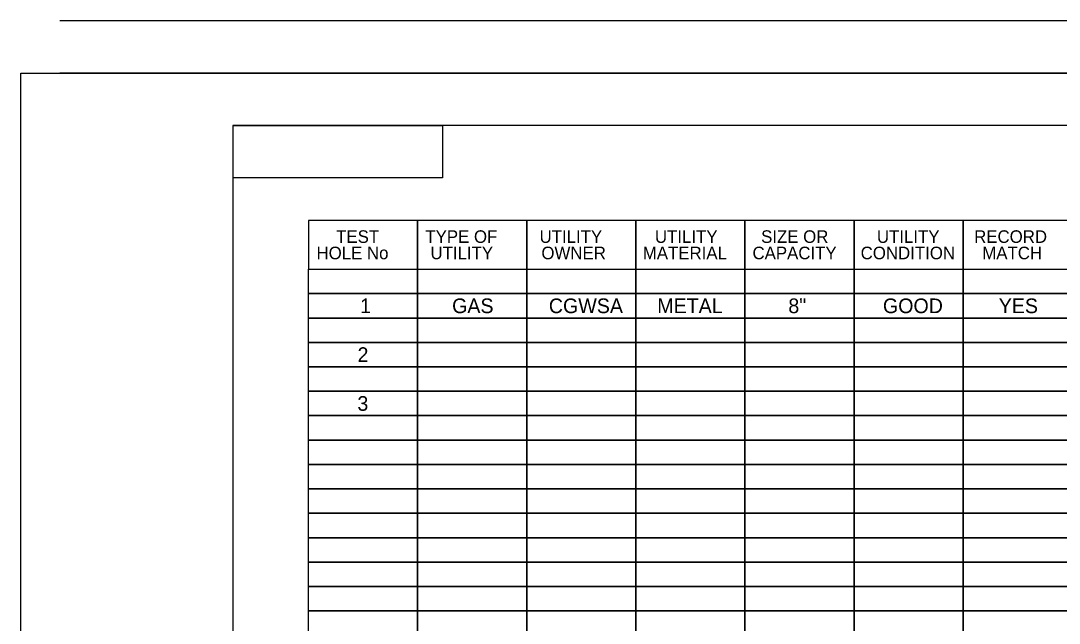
# Model space of a CAD drawing. Extents: x 14330 to 16126, y 15844 to 16994.
# Drawn here: x 14329.7 to 14825, y 16706 to 16993.6 of the extents above; entities that cross this region are included whole.
import ezdxf

# ---------------------------------------------------------------- set-up
doc = ezdxf.new("R2010")
doc.units = 0
for name, color, linetype in [('RD_SHT_Bndy', 7, 'Continuous'), ('RD_SHT_Iplotshp', 7, 'Continuous'), ('RD_SHT_Snap', 7, 'Continuous'), ('RD_SHT_TX', 7, 'Continuous')]:
    doc.layers.add(name, color=color, linetype=linetype)

msp = doc.modelspace()

# ---------------------------------------------------------------- linework, layer by layer
at = {"layer": 'RD_SHT_Bndy'}
for p, q in [((16108.25, 16993.63), (14348.25, 16993.63)), ((16108.25, 16968.63), (14348.25, 16968.63)), ((16105.85, 16943.63), (14430.85, 16943.63)), ((14430.85, 16943.63), (14430.85, 15893.63))]:
    msp.add_line(p, q, dxfattribs=at)
for points in [[(14430.9, 16918.63), (14430.9, 16943.63), (14530.9, 16943.63), (14530.9, 16918.63)], [(14466.94, 16875.02), (14518.98, 16875.02), (14518.98, 16898.33), (14466.94, 16898.33)], [(14518.98, 16875.02), (14571.02, 16875.02), (14571.02, 16898.33), (14518.98, 16898.33)], [(14571.02, 16875.02), (14623.07, 16875.02), (14623.07, 16898.33), (14571.02, 16898.33)], [(14623.07, 16875.02), (14675.11, 16875.02), (14675.11, 16898.33), (14623.07, 16898.33)], [(14675.11, 16875.02), (14727.15, 16875.02), (14727.15, 16898.33), (14675.11, 16898.33)], [(14727.15, 16875.02), (14779.19, 16875.02), (14779.19, 16898.33), (14727.15, 16898.33)], [(14779.19, 16875.02), (14831.23, 16875.02), (14831.23, 16898.33), (14779.19, 16898.33)], [(14518.98, 16863.36), (14466.94, 16863.36), (14466.94, 16875.02), (14518.98, 16875.02)], [(14571.02, 16863.36), (14518.98, 16863.36), (14518.98, 16875.02), (14571.02, 16875.02)], [(14623.07, 16863.36), (14571.02, 16863.36), (14571.02, 16875.02), (14623.07, 16875.02)], [(14675.11, 16863.36), (14623.07, 16863.36), (14623.07, 16875.02), (14675.11, 16875.02)], [(14727.15, 16863.36), (14675.11, 16863.36), (14675.11, 16875.02), (14727.15, 16875.02)], [(14779.19, 16863.36), (14727.15, 16863.36), (14727.15, 16875.02), (14779.19, 16875.02)], [(14831.23, 16863.36), (14779.19, 16863.36), (14779.19, 16875.02), (14831.23, 16875.02)], [(14518.98, 16851.71), (14466.94, 16851.71), (14466.94, 16863.36), (14518.98, 16863.36)], [(14571.02, 16851.71), (14518.98, 16851.71), (14518.98, 16863.36), (14571.02, 16863.36)], [(14623.07, 16851.71), (14571.02, 16851.71), (14571.02, 16863.36), (14623.07, 16863.36)], [(14675.11, 16851.71), (14623.07, 16851.71), (14623.07, 16863.36), (14675.11, 16863.36)], [(14727.15, 16851.71), (14675.11, 16851.71), (14675.11, 16863.36), (14727.15, 16863.36)], [(14779.19, 16851.71), (14727.15, 16851.71), (14727.15, 16863.36), (14779.19, 16863.36)], [(14831.23, 16851.71), (14779.19, 16851.71), (14779.19, 16863.36), (14831.23, 16863.36)], [(14518.98, 16840.05), (14466.94, 16840.05), (14466.94, 16851.71), (14518.98, 16851.71)], [(14571.02, 16840.05), (14518.98, 16840.05), (14518.98, 16851.71), (14571.02, 16851.71)], [(14623.07, 16840.05), (14571.02, 16840.05), (14571.02, 16851.71), (14623.07, 16851.71)], [(14675.11, 16840.05), (14623.07, 16840.05), (14623.07, 16851.71), (14675.11, 16851.71)], [(14727.15, 16840.05), (14675.11, 16840.05), (14675.11, 16851.71), (14727.15, 16851.71)], [(14779.19, 16840.05), (14727.15, 16840.05), (14727.15, 16851.71), (14779.19, 16851.71)], [(14831.23, 16840.05), (14779.19, 16840.05), (14779.19, 16851.71), (14831.23, 16851.71)], [(14518.98, 16828.4), (14466.94, 16828.4), (14466.94, 16840.05), (14518.98, 16840.05)], [(14571.02, 16828.4), (14518.98, 16828.4), (14518.98, 16840.05), (14571.02, 16840.05)], [(14623.07, 16828.4), (14571.02, 16828.4), (14571.02, 16840.05), (14623.07, 16840.05)], [(14675.11, 16828.4), (14623.07, 16828.4), (14623.07, 16840.05), (14675.11, 16840.05)], [(14727.15, 16828.4), (14675.11, 16828.4), (14675.11, 16840.05), (14727.15, 16840.05)], [(14779.19, 16828.4), (14727.15, 16828.4), (14727.15, 16840.05), (14779.19, 16840.05)], [(14831.23, 16828.4), (14779.19, 16828.4), (14779.19, 16840.05), (14831.23, 16840.05)], [(14518.98, 16816.74), (14466.94, 16816.74), (14466.94, 16828.4), (14518.98, 16828.4)], [(14571.02, 16816.74), (14518.98, 16816.74), (14518.98, 16828.4), (14571.02, 16828.4)], [(14623.07, 16816.74), (14571.02, 16816.74), (14571.02, 16828.4), (14623.07, 16828.4)], [(14675.11, 16816.74), (14623.07, 16816.74), (14623.07, 16828.4), (14675.11, 16828.4)], [(14727.15, 16816.74), (14675.11, 16816.74), (14675.11, 16828.4), (14727.15, 16828.4)], [(14779.19, 16816.74), (14727.15, 16816.74), (14727.15, 16828.4), (14779.19, 16828.4)], [(14831.23, 16816.74), (14779.19, 16816.74), (14779.19, 16828.4), (14831.23, 16828.4)], [(14518.98, 16805.09), (14466.94, 16805.09), (14466.94, 16816.74), (14518.98, 16816.74)], [(14571.02, 16805.09), (14518.98, 16805.09), (14518.98, 16816.74), (14571.02, 16816.74)], [(14623.07, 16805.09), (14571.02, 16805.09), (14571.02, 16816.74), (14623.07, 16816.74)], [(14675.11, 16805.09), (14623.07, 16805.09), (14623.07, 16816.74), (14675.11, 16816.74)], [(14727.15, 16805.09), (14675.11, 16805.09), (14675.11, 16816.74), (14727.15, 16816.74)], [(14779.19, 16805.09), (14727.15, 16805.09), (14727.15, 16816.74), (14779.19, 16816.74)], [(14831.23, 16805.09), (14779.19, 16805.09), (14779.19, 16816.74), (14831.23, 16816.74)], [(14518.98, 16793.43), (14466.94, 16793.43), (14466.94, 16805.09), (14518.98, 16805.09)], [(14571.02, 16793.43), (14518.98, 16793.43), (14518.98, 16805.09), (14571.02, 16805.09)], [(14623.07, 16793.43), (14571.02, 16793.43), (14571.02, 16805.09), (14623.07, 16805.09)], [(14675.11, 16793.43), (14623.07, 16793.43), (14623.07, 16805.09), (14675.11, 16805.09)], [(14727.15, 16793.43), (14675.11, 16793.43), (14675.11, 16805.09), (14727.15, 16805.09)], [(14779.19, 16793.43), (14727.15, 16793.43), (14727.15, 16805.09), (14779.19, 16805.09)], [(14831.23, 16793.43), (14779.19, 16793.43), (14779.19, 16805.09), (14831.23, 16805.09)], [(14518.98, 16781.78), (14466.94, 16781.78), (14466.94, 16793.43), (14518.98, 16793.43)], [(14571.02, 16781.78), (14518.98, 16781.78), (14518.98, 16793.43), (14571.02, 16793.43)], [(14623.07, 16781.78), (14571.02, 16781.78), (14571.02, 16793.43), (14623.07, 16793.43)], [(14675.11, 16781.78), (14623.07, 16781.78), (14623.07, 16793.43), (14675.11, 16793.43)], [(14727.15, 16781.78), (14675.11, 16781.78), (14675.11, 16793.43), (14727.15, 16793.43)], [(14779.19, 16781.78), (14727.15, 16781.78), (14727.15, 16793.43), (14779.19, 16793.43)], [(14831.23, 16781.78), (14779.19, 16781.78), (14779.19, 16793.43), (14831.23, 16793.43)], [(14518.98, 16770.12), (14466.94, 16770.12), (14466.94, 16781.78), (14518.98, 16781.78)], [(14571.02, 16770.12), (14518.98, 16770.12), (14518.98, 16781.78), (14571.02, 16781.78)], [(14623.07, 16770.12), (14571.02, 16770.12), (14571.02, 16781.78), (14623.07, 16781.78)], [(14675.11, 16770.12), (14623.07, 16770.12), (14623.07, 16781.78), (14675.11, 16781.78)], [(14727.15, 16770.12), (14675.11, 16770.12), (14675.11, 16781.78), (14727.15, 16781.78)], [(14779.19, 16770.12), (14727.15, 16770.12), (14727.15, 16781.78), (14779.19, 16781.78)], [(14831.23, 16770.12), (14779.19, 16770.12), (14779.19, 16781.78), (14831.23, 16781.78)], [(14518.98, 16758.47), (14466.94, 16758.47), (14466.94, 16770.12), (14518.98, 16770.12)], [(14571.02, 16758.47), (14518.98, 16758.47), (14518.98, 16770.12), (14571.02, 16770.12)], [(14623.07, 16758.47), (14571.02, 16758.47), (14571.02, 16770.12), (14623.07, 16770.12)], [(14675.11, 16758.47), (14623.07, 16758.47), (14623.07, 16770.12), (14675.11, 16770.12)], [(14727.15, 16758.47), (14675.11, 16758.47), (14675.11, 16770.12), (14727.15, 16770.12)], [(14779.19, 16758.47), (14727.15, 16758.47), (14727.15, 16770.12), (14779.19, 16770.12)], [(14831.23, 16758.47), (14779.19, 16758.47), (14779.19, 16770.12), (14831.23, 16770.12)], [(14518.98, 16746.81), (14466.94, 16746.81), (14466.94, 16758.47), (14518.98, 16758.47)], [(14571.02, 16746.81), (14518.98, 16746.81), (14518.98, 16758.47), (14571.02, 16758.47)], [(14623.07, 16746.81), (14571.02, 16746.81), (14571.02, 16758.47), (14623.07, 16758.47)], [(14675.11, 16746.81), (14623.07, 16746.81), (14623.07, 16758.47), (14675.11, 16758.47)], [(14727.15, 16746.81), (14675.11, 16746.81), (14675.11, 16758.47), (14727.15, 16758.47)], [(14779.19, 16746.81), (14727.15, 16746.81), (14727.15, 16758.47), (14779.19, 16758.47)], [(14831.23, 16746.81), (14779.19, 16746.81), (14779.19, 16758.47), (14831.23, 16758.47)], [(14518.98, 16735.16), (14466.94, 16735.16), (14466.94, 16746.81), (14518.98, 16746.81)], [(14571.02, 16735.16), (14518.98, 16735.16), (14518.98, 16746.81), (14571.02, 16746.81)], [(14623.07, 16735.16), (14571.02, 16735.16), (14571.02, 16746.81), (14623.07, 16746.81)], [(14675.11, 16735.16), (14623.07, 16735.16), (14623.07, 16746.81), (14675.11, 16746.81)], [(14727.15, 16735.16), (14675.11, 16735.16), (14675.11, 16746.81), (14727.15, 16746.81)], [(14779.19, 16735.16), (14727.15, 16735.16), (14727.15, 16746.81), (14779.19, 16746.81)], [(14831.23, 16735.16), (14779.19, 16735.16), (14779.19, 16746.81), (14831.23, 16746.81)], [(14518.98, 16723.5), (14466.94, 16723.5), (14466.94, 16735.16), (14518.98, 16735.16)], [(14571.02, 16723.5), (14518.98, 16723.5), (14518.98, 16735.16), (14571.02, 16735.16)], [(14623.07, 16723.5), (14571.02, 16723.5), (14571.02, 16735.16), (14623.07, 16735.16)], [(14675.11, 16723.5), (14623.07, 16723.5), (14623.07, 16735.16), (14675.11, 16735.16)], [(14727.15, 16723.5), (14675.11, 16723.5), (14675.11, 16735.16), (14727.15, 16735.16)], [(14779.19, 16723.5), (14727.15, 16723.5), (14727.15, 16735.16), (14779.19, 16735.16)], [(14831.23, 16723.5), (14779.19, 16723.5), (14779.19, 16735.16), (14831.23, 16735.16)], [(14518.98, 16711.84), (14466.94, 16711.84), (14466.94, 16723.5), (14518.98, 16723.5)], [(14571.02, 16711.84), (14518.98, 16711.84), (14518.98, 16723.5), (14571.02, 16723.5)], [(14623.07, 16711.84), (14571.02, 16711.84), (14571.02, 16723.5), (14623.07, 16723.5)], [(14675.11, 16711.84), (14623.07, 16711.84), (14623.07, 16723.5), (14675.11, 16723.5)], [(14727.15, 16711.84), (14675.11, 16711.84), (14675.11, 16723.5), (14727.15, 16723.5)], [(14779.19, 16711.84), (14727.15, 16711.84), (14727.15, 16723.5), (14779.19, 16723.5)], [(14831.23, 16711.84), (14779.19, 16711.84), (14779.19, 16723.5), (14831.23, 16723.5)], [(14518.98, 16700.19), (14466.94, 16700.19), (14466.94, 16711.84), (14518.98, 16711.84)], [(14571.02, 16700.19), (14518.98, 16700.19), (14518.98, 16711.84), (14571.02, 16711.84)], [(14623.07, 16700.19), (14571.02, 16700.19), (14571.02, 16711.84), (14623.07, 16711.84)], [(14675.11, 16700.19), (14623.07, 16700.19), (14623.07, 16711.84), (14675.11, 16711.84)], [(14727.15, 16700.19), (14675.11, 16700.19), (14675.11, 16711.84), (14727.15, 16711.84)], [(14779.19, 16700.19), (14727.15, 16700.19), (14727.15, 16711.84), (14779.19, 16711.84)], [(14831.23, 16700.19), (14779.19, 16700.19), (14779.19, 16711.84), (14831.23, 16711.84)]]:
    msp.add_lwpolyline(points, close=True, dxfattribs=at)
at = {"layer": 'RD_SHT_Iplotshp'}
msp.add_lwpolyline([(14329.65, 16968.63), (16125.65, 16968.63), (16125.65, 15868.63), (14329.65, 15868.63)], close=True, dxfattribs=at)
at = {"layer": 'RD_SHT_Snap'}
msp.add_line((14329.65, 15868.63), (14329.65, 16968.63), dxfattribs=at)

# ---------------------------------------------------------------- texts
at = {"layer": 'RD_SHT_TX'}
for s, height, p in [('TEST', 6, (14480.09, 16887.58)), ('TYPE OF', 6, (14522.66, 16887.58)), ('UTILITY', 6, (14577.13, 16887.58)), ('UTILITY', 6, (14632.17, 16887.58)), ('SIZE OR', 6, (14682.81, 16887.58)), ('UTILITY', 6, (14738.06, 16887.58)), ('RECORD', 6, (14784.44, 16887.58)), ('HOLE No', 6, (14470.73, 16879.77)), ('UTILITY', 6, (14525.09, 16879.77)), ('OWNER', 6, (14578.01, 16879.77)), ('MATERIAL', 6, (14626.38, 16879.77)), ('CAPACITY', 6, (14678.71, 16879.77)), ('CONDITION', 6, (14730.3, 16879.77)), ('MATCH', 6, (14788.32, 16879.77)), ('1', 7, (14491.5, 16854.03)), ('GAS', 7, (14535.41, 16854.03)), ('CGWSA', 7, (14581.56, 16854.03)), ('METAL', 7, (14633.27, 16854.03)), ('8"', 7, (14695.81, 16854.03)), ('GOOD', 7, (14740.93, 16854.03)), ('YES', 7, (14796.17, 16854.03)), ('2', 7, (14490.29, 16830.72)), ('3', 7, (14490.23, 16807.41))]:
    msp.add_text(s, height=height, dxfattribs=at).set_placement(p)

doc.saveas('drawing.dxf')
